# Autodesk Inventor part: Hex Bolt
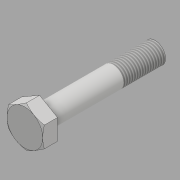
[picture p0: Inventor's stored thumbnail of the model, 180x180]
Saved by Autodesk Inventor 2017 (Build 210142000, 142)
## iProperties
Created: 2016-05
Part Number: Hex Bolt
Material: Generic
Document SubType Name: Modeling
Designer: CADCIM
Density: 1 g/cm^3
Appearance: Default
Author: CADCIM
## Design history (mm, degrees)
sketch "Sketch1"
  geometry: L1 (0, -19.63)-(-17, -9.815); L2 (-17, -9.815)-(-17, 9.815); L3 (-17, 9.815)-(0, 19.63); L4 (0, 19.63)-(17, 9.815); L5 (17, 9.815)-(17, -9.815); L6 (17, -9.815)-(0, -19.63); 2 further points
  constraints: 12 end point, 1 coincident, 13 other
  dimensions: "d0" = 34 distance between parallel lines of L2 L5
extrude "Extrusion1" new body sketch "Sketch1" distance "d1" = 14; taper "d2" = 0 deg
sketch "Sketch2"
  geometry: 1 further point
sketch "Sketch3"
  geometry: C1 r 10 at (0, 0); 1 further point
  constraints: 1 centre point, 1 coincident
  dimensions: "d3" = 20 diameter of C1
extrude "Extrusion2" join sketch "Sketch3" distance "d4" = 110; taper "d5" = 0 deg
thread "Thread1" dims "d6" = 40, "d7" = 0
sketch "Sketch4"
  geometry: L1 (0, -19.63)-(17, -9.815) reference; C1 r 17 at (0, 0); 1 further point
  constraints: 1 centre point, 1 coincident, 1 tangent
extrude "Extrusion3" sketch "Sketch4" distance "d8" = 200; taper "d9" = 60 deg
body "Solid1"
